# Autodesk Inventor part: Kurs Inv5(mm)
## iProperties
Author: Tobben
Created: 2001-12
Part Number: Kurs Inv5(mm)
Material: Steel, Mild
Document SubType Name: Modeling
Designer: Tobben
Control State: 0
Master: False
Checked Out: False
PropertySet Name: Design Tracking Control
Shininess: 64.0
Angle Display Precision: 2
Document Length Units: 11269
Document Angle Units: 11283
Document Time Units: 11279
Document Mass Units: 11290
Document Length Units Precision: 3
Document Angle Units Precision: 2
Compacted: True
PropertySet Name: _Private Model Information
Density: 0.0
Volumn: 0.0
Area: 0.0
PropertySet Name: Model Information
